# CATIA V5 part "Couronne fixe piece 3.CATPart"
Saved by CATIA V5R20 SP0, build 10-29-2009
Part number: Couronne fixe piece 3
Bounding box of the stored display mesh (mm): x -23.917 to 23.917, y 0 to 60, z -23.917 to 23.917
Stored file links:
  G:\Khaled_CFAO_2011\SIL\SIL_GR1\blaboucarri\Khaled\CAD_CATIA\Couronne fixe piece 3.CATPart
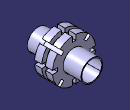
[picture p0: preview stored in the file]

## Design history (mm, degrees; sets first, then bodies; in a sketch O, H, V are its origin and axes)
Parameters
  `rayon base ` = 12 mm
  `rayon intérieur` = 11 mm
  `hauteur ` = 20 mm
  `petite hauteur` = 8 mm
  `hauteur intermediaire` = 4 mm
  `rayon max ` = 24 mm
  `profondeur rainure couronna` = 5 mm
Body1 (main body)
  Sketch1 on xy-plane, origin (0, 0, 0), H (1, 0, 0), V (0, 1, 0)
    line L1 (0, 0) -> (-12, 0)
    line L2 (-12, 0) -> (-12, 20)
    line L3 (-12, 20) -> (-24, 20)
    line L4 (-24, 20) -> (-24, 28)
    line L5 (-24, 28) -> (-19, 28)
    line L6 (-19, 28) -> (-19, 32)
    line L7 (-19, 32) -> (-24, 32)
    point P7 (-24, 32)
    line L8 (-24, 32) -> (-24, 40)
    line L9 (-24, 40) -> (-12, 40)
    point P9 (-12, 40)
    line L10 (-12, 40) -> (-12, 60)
    line L11 (-12, 60) -> (0, 60)
    point P11 (0, 60)
    line L12 (0, 60) -> (0, 0)
    length L11 = 12 {= `rayon base `}
    length L8 = 8 {= `petite hauteur`}
    length L4 = 8 {= `petite hauteur`}
    length L6 = 4 {= `hauteur intermediaire`}
    length L5 = 5 {= `profondeur rainure couronna`}
    length L10 = 20 {= `hauteur `}
    length L2 = 20 {= `hauteur `}
    distance L8 L12 = 24 {= `rayon max `}
    horizontal: L1 H, L3 H, L5 H, L7 H, L9 H, L11 H
    vertical: L2 V, L4 V, L6 V, L8 V, L10 V, L12 V
    coincidence: P7 L4, P9 L2, P11 V
  Shaft1: profile Sketch1, axis Sketch1.L12, angle 360
  Sketch2 on face of Shaft1 from Sketch1.L11, origin (0, 60, 0), H (1, 0, 0), V (0, 0, -1)
    point P1 (0, 0)
  Hole1: placed by Sketch2, at (0, 60, 0) direction (0, -1, 0), diameter 22 {= 2*`rayon intérieur`}, depth 50
  Sketch3 on face of Shaft1 from Sketch1.L3, origin (0, 20, 0), H (1, 0, 0), V (0, 0, 1)
    line L1 (-2, 33) -> (2, 33)
    line L2 (2, 33) -> (2, 18)
    line L3 (2, 18) -> (-2, 18)
    line L4 (-2, 18) -> (-2, 33)
    axis line L5 (0, 0) -> (0, 30.8032)
    distance O L3 = 18
    length L1 = 4
    length L4 = 15
    horizontal: L1 H, L3 H
    vertical: L2 V, L4 V, L5 V
    symmetry: L2 L4 L5
  Pocket1: profile Sketch3, direction (0, 1, 0), up to face of Shaft1 from Sketch1.L9
  CircPattern1: of Pocket1, instances 8, angular step 45, axis from face of Shaft1 from Sketch1.L2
